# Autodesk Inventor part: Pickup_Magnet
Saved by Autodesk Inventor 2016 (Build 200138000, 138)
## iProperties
Created: 2016-01
Part Number: Pickup_Magnet
Material: Generic
Document SubType Name: Modeling
Designer: Juha-Pekka
Density: 1 g/cm^3
Appearance: Default
Author: Juha-Pekka
Revision Number: ANY
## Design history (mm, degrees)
fillet "Fillet1"
body "Solid1"
